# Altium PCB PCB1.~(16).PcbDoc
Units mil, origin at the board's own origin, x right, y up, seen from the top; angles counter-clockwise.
Board outline 5880 x 2260 mil, 2 copper layers (Top Layer, Bottom Layer); 100 components, 175 nets, 460 pads, 120 vias.
Unrouted connection lines stored in the file: 16.
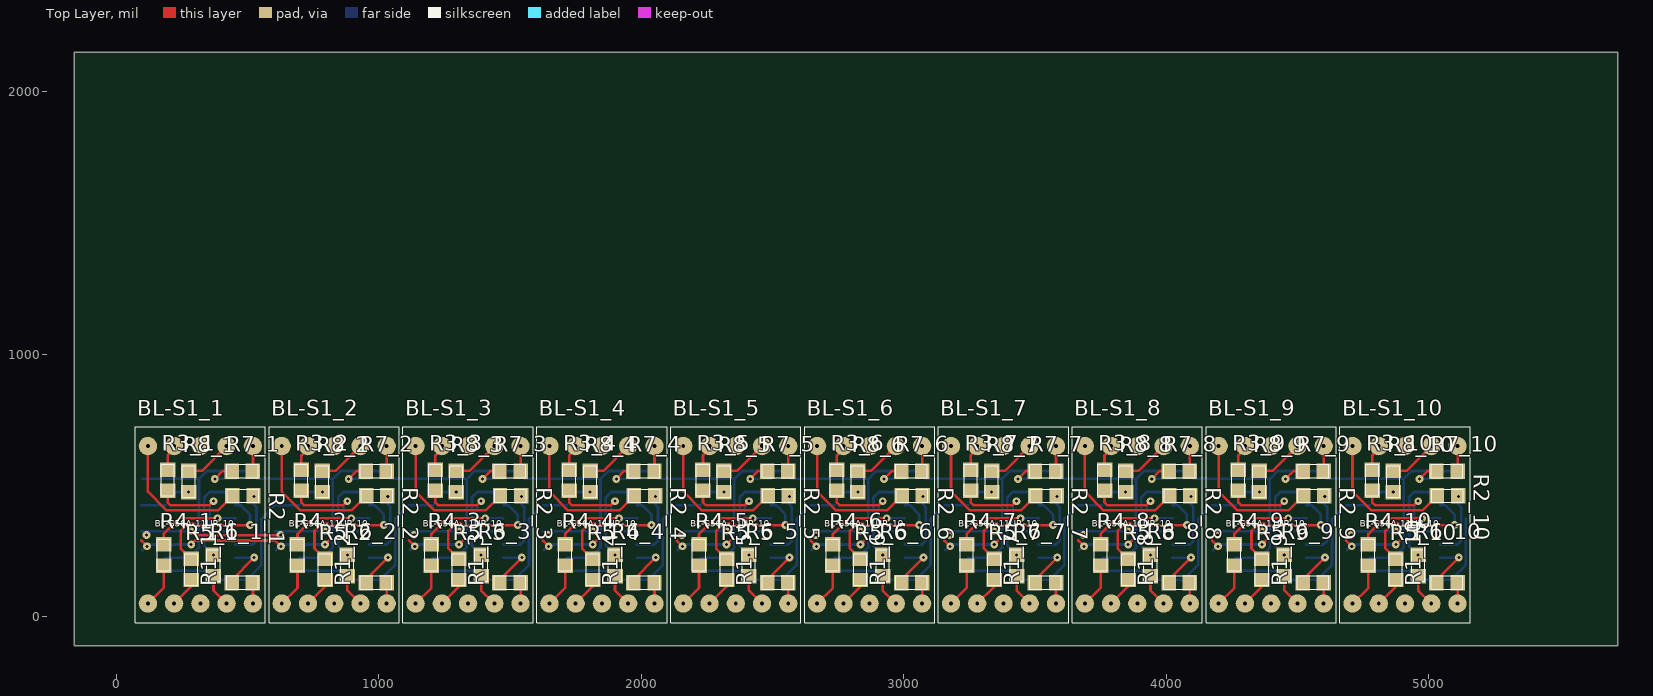
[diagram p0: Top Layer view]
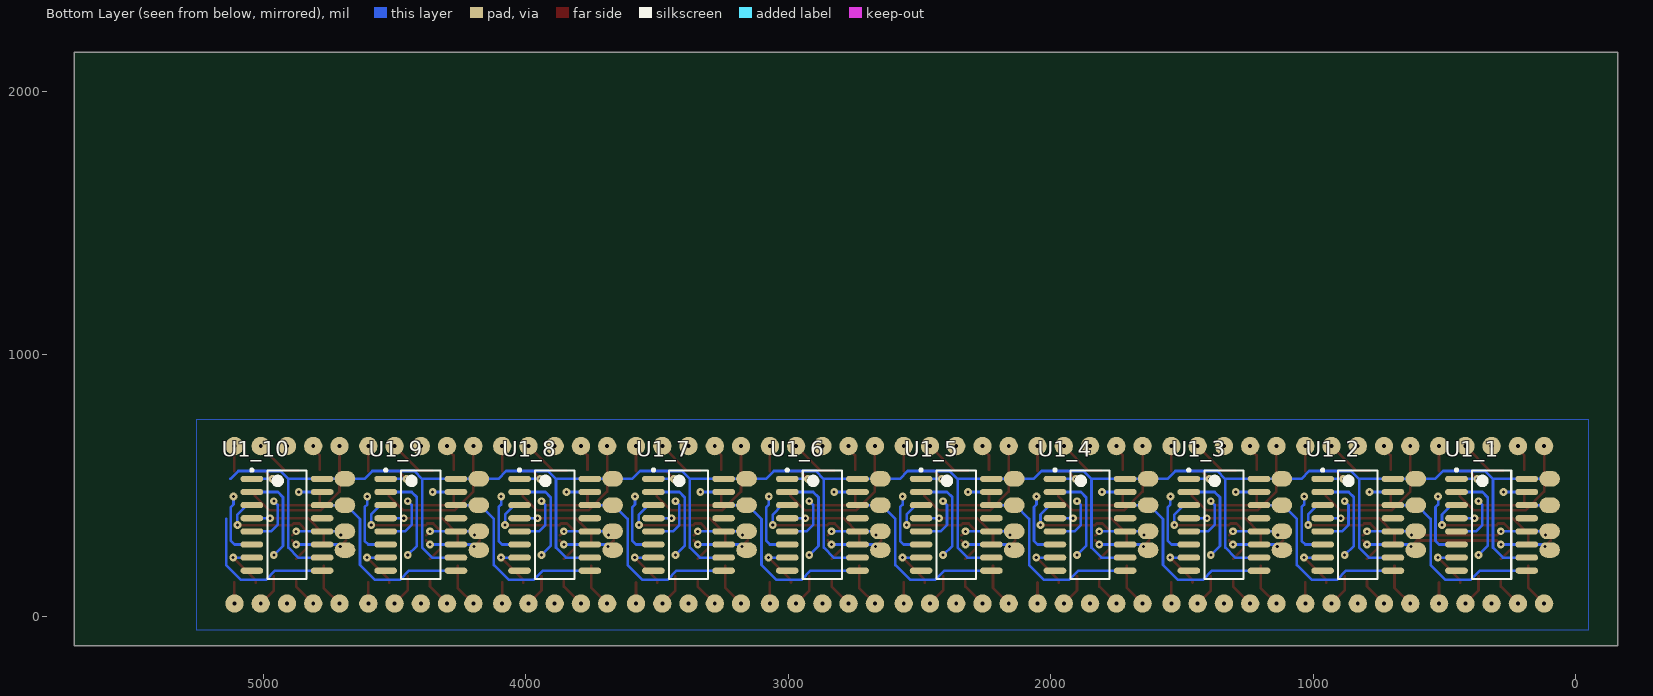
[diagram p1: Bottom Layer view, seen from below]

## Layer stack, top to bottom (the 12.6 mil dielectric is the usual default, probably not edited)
Top Solder: solder mask 0.4, Solder Resist, Dk 3.5
Top Layer: signal copper 1.4
Dielectric 1: dielectric 12.6, FR-4, Dk 4.8
Bottom Layer: signal copper 1.4
Bottom Solder: solder mask 0.4, Solder Resist, Dk 3.5

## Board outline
-160,-110 -160,2150 5720,2150 5720,-110 1430,-110

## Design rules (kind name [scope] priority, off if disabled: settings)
Clearance [All] p1: gap=5
MinimumSolderMaskSliver [All] p1 off: minsoldermaskwidth=10
PolygonConnect [All] p1: connectstyle=Relief reliefconductorwidth=10 reliefentries=4 polygonreliefangle="90 Angle" airgapwidth=15
RoomDefinition 10 [InComponentClass('10')] p1: confinementstyle=ConfineIn formatcopy=TRUE lockcomponents=TRUE outline 4645,-50 4645,750 5162,750 5162,-50
RoomDefinition 9 [InComponentClass('9')] p2: confinementstyle=ConfineIn formatcopy=TRUE lockcomponents=TRUE outline 4135,-50 4135,750 4652,750 4652,-50
RoomDefinition 8 [InComponentClass('8')] p3: confinementstyle=ConfineIn formatcopy=TRUE lockcomponents=TRUE outline 3625,-50 3625,750 4142,750 4142,-50
RoomDefinition 7 [InComponentClass('7')] p4: confinementstyle=ConfineIn formatcopy=TRUE lockcomponents=TRUE outline 3115,-50 3115,750 3632,750 3632,-50
RoomDefinition 6 [InComponentClass('6')] p5: confinementstyle=ConfineIn formatcopy=TRUE lockcomponents=TRUE outline 2605,-50 2605,750 3122,750 3122,-50
RoomDefinition 5 [InComponentClass('5')] p6: confinementstyle=ConfineIn formatcopy=TRUE lockcomponents=TRUE outline 2095,-50 2095,750 2612,750 2612,-50
RoomDefinition 4 [InComponentClass('4')] p7: confinementstyle=ConfineIn formatcopy=TRUE lockcomponents=TRUE outline 1585,-50 1585,750 2102,750 2102,-50
RoomDefinition 2 [InComponentClass('2')] p8: confinementstyle=ConfineIn formatcopy=TRUE lockcomponents=TRUE outline 565,-50 565,750 1082,750 1082,-50
RoomDefinition 1 [InComponentClass('1')] p9: confinementstyle=ConfineIn formatcopy=TRUE lockcomponents=FALSE outline 55,-50 55,750 572,750 572,-50
RoomDefinition 3 [InComponentClass('3')] p10: confinementstyle=ConfineIn formatcopy=TRUE lockcomponents=TRUE outline 1075,-50 1075,750 1592,750 1592,-50
RoutingVias [All] p1: holewidth=11.81 width=29.53 viastyle="Through Hole" minholewidth=11.81 minwidth=29.53 maxholewidth=28 maxwidth=70
SilkToBoardRegionClearance [All] p1 off:
SilkToSilkClearance [All] p1 off: silktosilkclearance=10
SilkToSolderMaskClearance [IsPad] p1 off: minsilkscreentomaskgap=10 clearancetoexposedcopper=TRUE
SolderMaskExpansion [All] p1: expansion=4
Width [All] p1: maxlimit=10 minlimit=7.87 preferedwidth=10
26 further rules are at their usual default settings.

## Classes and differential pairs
component class 6: BL-S1_6 R1_6 R2_6 R3_6 R4_6 R5_6 R6_6 R7_6 R8_6 U1_6
component class 5: BL-S1_5 R1_5 R2_5 R3_5 R4_5 R5_5 R6_5 R7_5 R8_5 U1_5
component class 1: BL-S1_1 R1_1 R2_1 R3_1 R4_1 R5_1 R6_1 R7_1 R8_1 U1_1
component class 2: BL-S1_2 R1_2 R2_2 R3_2 R4_2 R5_2 R6_2 R7_2 R8_2 U1_2
component class 3: BL-S1_3 R1_3 R2_3 R3_3 R4_3 R5_3 R6_3 R7_3 R8_3 U1_3
component class 4: BL-S1_4 R1_4 R2_4 R3_4 R4_4 R5_4 R6_4 R7_4 R8_4 U1_4
channel class Sheet2: 1 2 3 4 5 6 7 8 9 10
component class 7: BL-S1_7 R1_7 R2_7 R3_7 R4_7 R5_7 R6_7 R7_7 R8_7 U1_7
component class 8: BL-S1_8 R1_8 R2_8 R3_8 R4_8 R5_8 R6_8 R7_8 R8_8 U1_8
component class 9: BL-S1_9 R1_9 R2_9 R3_9 R4_9 R5_9 R6_9 R7_9 R8_9 U1_9
component class 10: BL-S1_10 R1_10 R2_10 R3_10 R4_10 R5_10 R6_10 R7_10 R8_10 U1_10

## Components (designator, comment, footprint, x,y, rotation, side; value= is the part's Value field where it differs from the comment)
BL-S1_1 "BL-S56A-11UR" BL-S56A-11UR 71.97,350 r0 top (schematic designator BL-S1)
BL-S1_2 "BL-S56A-11UR" BL-S56A-11UR 581.97,350 r0 top locked (schematic designator BL-S1)
BL-S1_3 "BL-S56A-11UR" BL-S56A-11UR 1091.97,350 r0 top (schematic designator BL-S1)
BL-S1_4 "BL-S56A-11UR" BL-S56A-11UR 1601.97,350 r0 top (schematic designator BL-S1)
BL-S1_5 "BL-S56A-11UR" BL-S56A-11UR 2111.97,350 r0 top (schematic designator BL-S1)
BL-S1_6 "BL-S56A-11UR" BL-S56A-11UR 2621.97,350 r0 top (schematic designator BL-S1)
BL-S1_7 "BL-S56A-11UR" BL-S56A-11UR 3131.97,350 r0 top (schematic designator BL-S1)
BL-S1_8 "BL-S56A-11UR" BL-S56A-11UR 3641.97,350 r0 top (schematic designator BL-S1)
BL-S1_9 "BL-S56A-11UR" BL-S56A-11UR 4151.97,350 r0 top (schematic designator BL-S1)
BL-S1_10 "BL-S56A-11UR" BL-S56A-11UR 4661.97,350 r0 top (schematic designator BL-S1)
R1_1 "310R" Res0805 480,130 r180 top (schematic designator R1)
R1_2 "310R" Res0805 990,130 r180 top (schematic designator R1)
R1_3 "310R" Res0805 1500,130 r180 top (schematic designator R1)
R1_4 "310R" Res0805 2010,130 r180 top (schematic designator R1)
R1_5 "310R" Res0805 2520,130 r180 top (schematic designator R1)
R1_6 "310R" Res0805 3030,130 r180 top (schematic designator R1)
R1_7 "310R" Res0805 3540,130 r180 top (schematic designator R1)
R1_8 "310R" Res0805 4050,130 r180 top (schematic designator R1)
R1_9 "310R" Res0805 4560,130 r180 top (schematic designator R1)
R1_10 "310R" Res0805 5070,130 r180 top (schematic designator R1)
R2_1 "310R" Res0805 482.05,460 r0 top (schematic designator R2)
R2_2 "310R" Res0805 992.05,460 r0 top (schematic designator R2)
R2_3 "310R" Res0805 1502.05,460 r0 top (schematic designator R2)
R2_4 "310R" Res0805 2012.05,460 r0 top (schematic designator R2)
R2_5 "310R" Res0805 2522.05,460 r0 top (schematic designator R2)
R2_6 "310R" Res0805 3032.05,460 r0 top (schematic designator R2)
R2_7 "310R" Res0805 3542.05,460 r0 top (schematic designator R2)
R2_8 "310R" Res0805 4052.05,460 r0 top (schematic designator R2)
R2_9 "310R" Res0805 4562.05,460 r0 top (schematic designator R2)
R2_10 "310R" Res0805 5072.05,460 r0 top (schematic designator R2)
R3_1 "310R" Res0805 195,520 r270 top (schematic designator R3)
R3_2 "310R" Res0805 705,520 r270 top (schematic designator R3)
R3_3 "310R" Res0805 1215,520 r270 top (schematic designator R3)
R3_4 "310R" Res0805 1725,520 r270 top (schematic designator R3)
R3_5 "310R" Res0805 2235,520 r270 top (schematic designator R3)
R3_6 "310R" Res0805 2745,520 r270 top (schematic designator R3)
R3_7 "310R" Res0805 3255,520 r270 top (schematic designator R3)
R3_8 "310R" Res0805 3765,520 r270 top (schematic designator R3)
R3_9 "310R" Res0805 4275,520 r270 top (schematic designator R3)
R3_10 "310R" Res0805 4785,520 r270 top (schematic designator R3)
R4_1 "310R" Res0805 180,235 r90 top (schematic designator R4)
R4_2 "310R" Res0805 690,235 r90 top (schematic designator R4)
R4_3 "310R" Res0805 1200,235 r90 top (schematic designator R4)
R4_4 "310R" Res0805 1710,235 r90 top (schematic designator R4)
R4_5 "310R" Res0805 2220,235 r90 top (schematic designator R4)
R4_6 "310R" Res0805 2730,235 r90 top (schematic designator R4)
R4_7 "310R" Res0805 3240,235 r90 top (schematic designator R4)
R4_8 "310R" Res0805 3750,235 r90 top (schematic designator R4)
R4_9 "310R" Res0805 4260,235 r90 top (schematic designator R4)
R4_10 "310R" Res0805 4770,235 r90 top (schematic designator R4)
R5_1 "310R" Res0805 285,180 r90 top (schematic designator R5)
R5_2 "310R" Res0805 795,180 r90 top (schematic designator R5)
R5_3 "310R" Res0805 1305,180 r90 top (schematic designator R5)
R5_4 "310R" Res0805 1815,180 r90 top (schematic designator R5)
R5_5 "310R" Res0805 2325,180 r90 top (schematic designator R5)
R5_6 "310R" Res0805 2835,180 r90 top (schematic designator R5)
R5_7 "310R" Res0805 3345,180 r90 top (schematic designator R5)
R5_8 "310R" Res0805 3855,180 r90 top (schematic designator R5)
R5_9 "310R" Res0805 4365,180 r90 top (schematic designator R5)
R5_10 "310R" Res0805 4875,180 r90 top (schematic designator R5)
R6_1 "310R" Res0805 370,195 r90 top (schematic designator R6)
R6_2 "310R" Res0805 880,195 r90 top (schematic designator R6)
R6_3 "310R" Res0805 1390,195 r90 top (schematic designator R6)
R6_4 "310R" Res0805 1900,195 r90 top (schematic designator R6)
R6_5 "310R" Res0805 2410,195 r90 top (schematic designator R6)
R6_6 "310R" Res0805 2920,195 r90 top (schematic designator R6)
R6_7 "310R" Res0805 3430,195 r90 top (schematic designator R6)
R6_8 "310R" Res0805 3940,195 r90 top (schematic designator R6)
R6_9 "310R" Res0805 4450,195 r90 top (schematic designator R6)
R6_10 "310R" Res0805 4960,195 r90 top (schematic designator R6)
R7_1 "310R" Res0805 480,555 r180 top (schematic designator R7)
R7_2 "310R" Res0805 990,555 r180 top (schematic designator R7)
R7_3 "310R" Res0805 1500,555 r180 top (schematic designator R7)
R7_4 "310R" Res0805 2010,555 r180 top (schematic designator R7)
R7_5 "310R" Res0805 2520,555 r180 top (schematic designator R7)
R7_6 "310R" Res0805 3030,555 r180 top (schematic designator R7)
R7_7 "310R" Res0805 3540,555 r180 top (schematic designator R7)
R7_8 "310R" Res0805 4050,555 r180 top (schematic designator R7)
R7_9 "310R" Res0805 4560,555 r180 top (schematic designator R7)
R7_10 "310R" Res0805 5070,555 r180 top (schematic designator R7)
R8_1 "310R" Res0805 275,515 r270 top (schematic designator R8)
R8_2 "310R" Res0805 785,515 r270 top (schematic designator R8)
R8_3 "310R" Res0805 1295,515 r270 top (schematic designator R8)
R8_4 "310R" Res0805 1805,515 r270 top (schematic designator R8)
R8_5 "310R" Res0805 2315,515 r270 top (schematic designator R8)
R8_6 "310R" Res0805 2825,515 r270 top (schematic designator R8)
R8_7 "310R" Res0805 3335,515 r270 top (schematic designator R8)
R8_8 "310R" Res0805 3845,515 r270 top (schematic designator R8)
R8_9 "310R" Res0805 4355,515 r270 top (schematic designator R8)
R8_10 "310R" Res0805 4865,515 r270 top (schematic designator R8)
U1_1 "HD74HC595FP" PRSP0016DH-B_N 320,350 r180 bottom (schematic designator U1)
U1_2 "HD74HC595FP" PRSP0016DH-B_N 830,350 r180 bottom (schematic designator U1)
U1_3 "HD74HC595FP" PRSP0016DH-B_N 1340,350 r180 bottom (schematic designator U1)
U1_4 "HD74HC595FP" PRSP0016DH-B_N 1850,350 r180 bottom (schematic designator U1)
U1_5 "HD74HC595FP" PRSP0016DH-B_N 2360,350 r180 bottom (schematic designator U1)
U1_6 "HD74HC595FP" PRSP0016DH-B_N 2870,350 r180 bottom (schematic designator U1)
U1_7 "HD74HC595FP" PRSP0016DH-B_N 3380,350 r180 bottom (schematic designator U1)
U1_8 "HD74HC595FP" PRSP0016DH-B_N 3890,350 r180 bottom (schematic designator U1)
U1_9 "HD74HC595FP" PRSP0016DH-B_N 4400,350 r180 bottom (schematic designator U1)
U1_10 "HD74HC595FP" PRSP0016DH-B_N 4910,350 r180 bottom (schematic designator U1)

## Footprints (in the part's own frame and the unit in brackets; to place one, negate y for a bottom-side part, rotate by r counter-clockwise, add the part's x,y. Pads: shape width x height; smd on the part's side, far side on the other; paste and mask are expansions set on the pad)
BL-S56A-11UR [mil]
  round 70 hole 15: 1(48.03,-300) 2(148.03,-300) 3(248.03,-300) 4(348.03,-300) 5(448.03,-300) 6(448.03,300) 7(348.03,300) 8(248.03,300) 9(148.03,300) 10(48.03,300)
  silkscreen extent 0,-374 496,374, body extent 0,-374 496,374, height 315
PRSP0016DH-B_N [mm] "SOP, 16-Leads, Body 10.06x5.5mm, Pitch 1.27mm, IPC Medium Density"
  oval 2.2x0.6 smd: 1(-3.4,4.445) 2(-3.4,3.175) 3(-3.4,1.905) 4(-3.4,0.635) 5(-3.4,-0.635) 6(-3.4,-1.905) 7(-3.4,-3.175) 8(-3.4,-4.445) 9(3.4,-4.445) 10(3.4,-3.175) 11(3.4,-1.905) 12(3.4,-0.635) 13(3.4,0.635) 14(3.4,1.905) 15(3.4,3.175) 16(3.4,4.445)
  silkscreen extent -3.52,-5.25 1.9,5.42, body extent -2.7,-5.25 2.7,5.25, height 2.2
Res0805 [mm]
  rect 1.4x1.5 smd: 1(-1.025,0) 2(1.025,0)
  silkscreen extent -1.52,-0.64 1.52,0.64, body extent -1.15,-0.67 1.15,0.68, height 0.76

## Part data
BL-S1_1 BL-S1_2 BL-S1_3 BL-S1_4 BL-S1_5 BL-S1_6 BL-S1_7 BL-S1_8 BL-S1_9 BL-S1_10: library part Component_1
R1_1 R1_2 R1_3 R1_4 R1_5 R1_6 R1_7 R1_8 R1_9 R1_10 R2_1 R2_2 R2_3 R2_4 R2_5 R2_6 R2_7 R2_8 R2_9 R2_10 R3_1 R3_2 R3_3 R3_4 R3_5 R3_6 R3_7 R3_8 R3_9 R3_10 R4_1 R4_2 R4_3 R4_4 R4_5 R4_6 R4_7 R4_8 R4_9 R4_10 R5_1 R5_2 R5_3 R5_4 R5_5 R5_6 R5_7 R5_8 R5_9 R5_10 R6_1 R6_2 R6_3 R6_4 R6_5 R6_6 R6_7 R6_8 R6_9 R6_10 R7_1 R7_2 R7_3 R7_4 R7_5 R7_6 R7_7 R7_8 R7_9 R7_10 R8_1 R8_2 R8_3 R8_4 R8_5 R8_6 R8_7 R8_8 R8_9 R8_10: library part Res1, "Resistor"
U1_1 U1_2 U1_3 U1_4 U1_5 U1_6 U1_7 U1_8 U1_9 U1_10: "8-bit Shift Register / Latch with 3-State Outputs"

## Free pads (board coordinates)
  oval 78.74x59.06 smd far side: 8(99.06,525) 8(609.06,525) 8(1119.06,525) 8(1629.06,525) 8(2139.06,525) 8(2649.06,525) 8(3159.06,525) 8(3669.06,525) 8(4179.06,525) 8(4689.06,525) 9(99.06,425) 9(609.06,425) 9(1119.06,425) 9(1629.06,425) 9(2139.06,425) 9(2649.06,425) 9(3159.06,425) 9(3669.06,425) 9(4179.06,425) 9(4689.06,425) 10(99.06,325) 10(609.06,325) 10(1119.06,325) 10(1629.06,325) 10(2139.06,325) 10(2649.06,325) 10(3159.06,325) 10(3669.06,325) 10(4179.06,325) 10(4689.06,325) 11(99,254) 11(609,254) 11(1119,254) 11(1629,254) 11(2139,254) 11(2649,254) 11(3159,254) 11(3669,254) 11(4179,254) 11(4689,254)

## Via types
v1: diameter 29.53, hole 11.81, Top Layer to Bottom Layer, tented both sides, 80 vias
v2: diameter 29.53, hole 11.81, Top Layer to Bottom Layer, 40 vias

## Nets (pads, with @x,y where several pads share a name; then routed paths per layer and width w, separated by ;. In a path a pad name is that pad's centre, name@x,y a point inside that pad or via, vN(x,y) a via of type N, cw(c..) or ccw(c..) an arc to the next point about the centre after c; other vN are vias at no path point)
+5V: pad.8 U1_1.10 U1_1.16 U1_2.10 U1_2.16 U1_3.10 U1_3.16 U1_4.10 U1_4.16 U1_5.10 U1_5.16 U1_6.10 U1_6.16 U1_7.10 U1_7.16 U1_8.10 U1_8.16 U1_9.10 U1_9.16 U1_10.10 U1_10.16 | length 9862.5
  Bottom Layer w10: pad.8@99.06,525 U1_1.16 315,525 345,555 505,555 535,525 U1_2.16 ; U1_1.10 277.09,225 314.76,262.67 314.76,525 ; pad.8@609.06,525 U1_2.16 ; U1_2.10 787.09,225 824.76,262.67 824.76,525 ; U1_3.10 1297.09,225 1334.76,262.67 1334.76,525 ; U1_4.10 1807.09,225 1844.76,262.67 1844.76,525 ; U1_5.10 2317.09,225 2354.76,262.67 2354.76,525 ; pad.8@2649.06,525 2865,525 2895,555 3055,555 3085,525 U1_7.16 ; U1_6.10 2827.09,225 2864.76,262.67 2864.76,525 ; U1_6.16 2575,525 2545,555 2385,555 2355,525 2139.06,525 2065,525 2035,555 1875,555 1845,525 U1_4.16 1629.06,525 1555,525 1525,555 1365,555 1335,525 U1_3.16 1119.06,525 1045,525 1015,555 855,555 825,525 U1_2.16 ; pad.8@3159.06,525 3375,525 3405,555 3565,555 3595,525 U1_8.16 ; U1_7.10 3337.09,225 3374.76,262.67 3374.76,525 ; pad.8@3669.06,525 3885,525 3915,555 4075,555 4105,525 U1_9.16 ; U1_8.10 3847.09,225 3884.76,262.67 3884.76,525 ; pad.8@4179.06,525 4395,525 4425,555 4585,555 4615,525 U1_10.16 ; U1_9.10 4357.09,225 4394.76,262.67 4394.76,525 ; pad.8@4689.06,525 4905,525 4935,555 5095,555 5125,525 ; U1_10.10 4867.09,225 4904.76,262.67 4904.76,525
GND: BL-S1_1.3 BL-S1_1.8 BL-S1_2.3 BL-S1_2.8 BL-S1_3.3 BL-S1_3.8 BL-S1_4.3 BL-S1_4.8 BL-S1_5.3 BL-S1_5.8 BL-S1_6.3 BL-S1_6.8 BL-S1_7.3 BL-S1_7.8 BL-S1_8.3 BL-S1_8.8 BL-S1_9.3 BL-S1_9.8 BL-S1_10.3 BL-S1_10.8 U1_1.8 U1_1.13 U1_2.8 U1_2.13 U1_3.8 U1_3.13 U1_4.8 U1_4.13 U1_5.8 U1_5.13 U1_6.8 U1_6.13 U1_7.8 U1_7.13 U1_8.8 U1_8.13 U1_9.8 U1_9.13 U1_10.8 U1_10.13
L_A_1: BL-S1_1.7 R8_1.1 | length 184.2
  Top Layer w10: R8_1.1 325.35,555.35 BL-S1_1.7
L_A_2: BL-S1_2.7 R8_2.1 | length 184.2
  Top Layer w10: R8_2.1 835.35,555.35 BL-S1_2.7
L_A_3: BL-S1_3.7 R8_3.1 | length 184.2
  Top Layer w10: R8_3.1 1345.35,555.35 BL-S1_3.7
L_A_4: BL-S1_4.7 R8_4.1 | length 184.2
  Top Layer w10: R8_4.1 1855.35,555.35 BL-S1_4.7
L_A_5: BL-S1_5.7 R8_5.1 | length 184.2
  Top Layer w10: R8_5.1 2365.36,555.36 BL-S1_5.7
L_A_6: BL-S1_6.7 R8_6.1 | length 184.2
  Top Layer w10: R8_6.1 2875.36,555.36 BL-S1_6.7
L_A_7: BL-S1_7.7 R8_7.1 | length 184.2
  Top Layer w10: R8_7.1 3385.36,555.36 BL-S1_7.7
L_A_8: BL-S1_8.7 R8_8.1 | length 184.2
  Top Layer w10: R8_8.1 3895.36,555.36 BL-S1_8.7
L_A_9: BL-S1_9.7 R8_9.1 | length 184.2
  Top Layer w10: R8_9.1 4405.36,555.36 BL-S1_9.7
L_A_10: BL-S1_10.7 R8_10.1 | length 184.2
  Top Layer w10: R8_10.1 4915.36,555.36 BL-S1_10.7
L_B_1: BL-S1_1.6 R7_1.1 | length 95.1
  Top Layer w10: BL-S1_1.6 520.35,649.65 R7_1.1
L_B_2: BL-S1_2.6 R7_2.1 | length 95.1
  Top Layer w10: BL-S1_2.6 1030.35,649.65 R7_2.1
L_B_3: BL-S1_3.6 R7_3.1 | length 95.1
  Top Layer w10: BL-S1_3.6 1540.35,649.65 R7_3.1
L_B_4: BL-S1_4.6 R7_4.1 | length 95.1
  Top Layer w10: BL-S1_4.6 2050.35,649.65 R7_4.1
L_B_5: BL-S1_5.6 R7_5.1 | length 95.1
  Top Layer w10: BL-S1_5.6 2560.35,649.65 R7_5.1
L_B_6: BL-S1_6.6 R7_6.1 | length 95.1
  Top Layer w10: BL-S1_6.6 3070.35,649.65 R7_6.1
L_B_7: BL-S1_7.6 R7_7.1 | length 95.1
  Top Layer w10: BL-S1_7.6 3580.35,649.65 R7_7.1
L_B_8: BL-S1_8.6 R7_8.1 | length 95.1
  Top Layer w10: BL-S1_8.6 4090.35,649.65 R7_8.1
L_B_9: BL-S1_9.6 R7_9.1 | length 95.1
  Top Layer w10: BL-S1_9.6 4600.35,649.65 R7_9.1
L_B_10: BL-S1_10.6 R7_10.1 | length 95.1
  Top Layer w10: BL-S1_10.6 5110.35,649.65 R7_10.1
L_C_1: BL-S1_1.4 R6_1.1 | length 125.4
  Top Layer w10: R6_1.1 370,100 BL-S1_1.4
L_C_2: BL-S1_2.4 R6_2.1 | length 125.4
  Top Layer w10: R6_2.1 880,100 BL-S1_2.4
L_C_3: BL-S1_3.4 R6_3.1 | length 125.4
  Top Layer w10: R6_3.1 1390,100 BL-S1_3.4
L_C_4: BL-S1_4.4 R6_4.1 | length 125.4
  Top Layer w10: R6_4.1 1900,100 BL-S1_4.4
L_C_5: BL-S1_5.4 R6_5.1 | length 125.4
  Top Layer w10: R6_5.1 2410,100 BL-S1_5.4
L_C_6: BL-S1_6.4 R6_6.1 | length 125.4
  Top Layer w10: R6_6.1 2920,100 BL-S1_6.4
L_C_7: BL-S1_7.4 R6_7.1 | length 125.4
  Top Layer w10: R6_7.1 3430,100 BL-S1_7.4
L_C_8: BL-S1_8.4 R6_8.1 | length 125.4
  Top Layer w10: R6_8.1 3940,100 BL-S1_8.4
L_C_9: BL-S1_9.4 R6_9.1 | length 125.4
  Top Layer w10: R6_9.1 4450,100 BL-S1_9.4
L_C_10: BL-S1_10.4 R6_10.1 | length 125.4
  Top Layer w10: R6_10.1 4960,100 BL-S1_10.4
L_D_1: BL-S1_1.2 R5_1.1 | length 111.6
  Top Layer w10: BL-S1_1.2 285,115 R5_1.1@285,134.65
L_D_2: BL-S1_2.2 R5_2.1 | length 111.6
  Top Layer w10: BL-S1_2.2 795,115 R5_2.1@795,134.65
L_D_3: BL-S1_3.2 R5_3.1 | length 111.6
  Top Layer w10: BL-S1_3.2 1305,115 R5_3.1@1305,134.65
L_D_4: BL-S1_4.2 R5_4.1 | length 111.6
  Top Layer w10: BL-S1_4.2 1815,115 R5_4.1@1815,134.65
L_D_5: BL-S1_5.2 R5_5.1 | length 111.6
  Top Layer w10: BL-S1_5.2 2325,115 R5_5.1@2325,134.65
L_D_6: BL-S1_6.2 R5_6.1 | length 111.6
  Top Layer w10: BL-S1_6.2 2835,115 R5_6.1@2835,134.65
L_D_7: BL-S1_7.2 R5_7.1 | length 111.6
  Top Layer w10: BL-S1_7.2 3345,115 R5_7.1@3345,134.65
L_D_8: BL-S1_8.2 R5_8.1 | length 111.6
  Top Layer w10: BL-S1_8.2 3855,115 R5_8.1@3855,134.65
L_D_9: BL-S1_9.2 R5_9.1 | length 111.6
  Top Layer w10: BL-S1_9.2 4365,115 R5_9.1@4365,134.65
L_D_10: BL-S1_10.2 R5_10.1 | length 111.6
  Top Layer w10: BL-S1_10.2 4875,115 R5_10.1@4875,134.65
L_E_1: BL-S1_1.1 R4_1.1 | length 169.5
  Top Layer w10: BL-S1_1.1 180,110 R4_1.1
L_E_2: BL-S1_2.1 R4_2.1 | length 169.5
  Top Layer w10: BL-S1_2.1 690,110 R4_2.1
L_E_3: BL-S1_3.1 R4_3.1 | length 169.5
  Top Layer w10: BL-S1_3.1 1200,110 R4_3.1
L_E_4: BL-S1_4.1 R4_4.1 | length 169.5
  Top Layer w10: BL-S1_4.1 1710,110 R4_4.1
L_E_5: BL-S1_5.1 R4_5.1 | length 169.5
  Top Layer w10: BL-S1_5.1 2220,110 R4_5.1
L_E_6: BL-S1_6.1 R4_6.1 | length 169.5
  Top Layer w10: BL-S1_6.1 2730,110 R4_6.1
L_E_7: BL-S1_7.1 R4_7.1 | length 169.5
  Top Layer w10: BL-S1_7.1 3240,110 R4_7.1
L_E_8: BL-S1_8.1 R4_8.1 | length 169.5
  Top Layer w10: BL-S1_8.1 3750,110 R4_8.1
L_E_9: BL-S1_9.1 R4_9.1 | length 169.5
  Top Layer w10: BL-S1_9.1 4260,110 R4_9.1
L_E_10: BL-S1_10.1 R4_10.1 | length 169.5
  Top Layer w10: BL-S1_10.1 4770,110 R4_10.1
L_F_1: BL-S1_1.9 R3_1.1 | length 100
  Top Layer w10: R3_1.1 195,615 220,640 BL-S1_1.9
L_F_2: BL-S1_2.9 R3_2.1 | length 100
  Top Layer w10: R3_2.1 705,615 730,640 BL-S1_2.9
L_F_3: BL-S1_3.9 R3_3.1 | length 100
  Top Layer w10: R3_3.1 1215,615 1240,640 BL-S1_3.9
L_F_4: BL-S1_4.9 R3_4.1 | length 100
  Top Layer w10: R3_4.1 1725,615 1750,640 BL-S1_4.9
L_F_5: BL-S1_5.9 R3_5.1 | length 100
  Top Layer w10: R3_5.1 2235,615 2260,640 BL-S1_5.9
L_F_6: BL-S1_6.9 R3_6.1 | length 100
  Top Layer w10: R3_6.1 2745,615 2770,640 BL-S1_6.9
L_F_7: BL-S1_7.9 R3_7.1 | length 100
  Top Layer w10: R3_7.1 3255,615 3280,640 BL-S1_7.9
L_F_8: BL-S1_8.9 R3_8.1 | length 100
  Top Layer w10: R3_8.1 3765,615 3790,640 BL-S1_8.9
L_F_9: BL-S1_9.9 R3_9.1 | length 100
  Top Layer w10: R3_9.1 4275,615 4300,640 BL-S1_9.9
L_F_10: BL-S1_10.9 R3_10.1 | length 100
  Top Layer w10: R3_10.1 4785,615 4810,640 BL-S1_10.9
L_G_1: BL-S1_1.10 R2_1.1 | length 547.9
  Top Layer w10: BL-S1_1.10 120,476.35 191.58,404.76 386.46,404.76 R2_1.1
L_G_2: BL-S1_2.10 R2_2.1 | length 547.9
  Top Layer w10: BL-S1_2.10 630,476.35 701.58,404.76 896.46,404.76 R2_2.1
L_G_3: BL-S1_3.10 R2_3.1 | length 547.9
  Top Layer w10: BL-S1_3.10 1140,476.35 1211.58,404.76 1406.46,404.76 R2_3.1
L_G_4: BL-S1_4.10 R2_4.1 | length 547.9
  Top Layer w10: BL-S1_4.10 1650,476.35 1721.58,404.76 1916.46,404.76 R2_4.1
L_G_5: BL-S1_5.10 R2_5.1 | length 547.9
  Top Layer w10: BL-S1_5.10 2160,476.35 2231.58,404.76 2426.46,404.76 R2_5.1
L_G_6: BL-S1_6.10 R2_6.1 | length 547.9
  Top Layer w10: BL-S1_6.10 2670,476.35 2741.58,404.76 2936.46,404.76 R2_6.1
L_G_7: BL-S1_7.10 R2_7.1 | length 547.9
  Top Layer w10: BL-S1_7.10 3180,476.35 3251.58,404.76 3446.46,404.76 R2_7.1
L_G_8: BL-S1_8.10 R2_8.1 | length 547.9
  Top Layer w10: BL-S1_8.10 3690,476.35 3761.58,404.76 3956.46,404.76 R2_8.1
L_G_9: BL-S1_9.10 R2_9.1 | length 547.9
  Top Layer w10: BL-S1_9.10 4200,476.35 4271.58,404.76 4466.46,404.76 R2_9.1
L_G_10: BL-S1_10.10 R2_10.1 | length 547.9
  Top Layer w10: BL-S1_10.10 4710,476.35 4781.58,404.76 4976.46,404.76 R2_10.1
L_H_1: BL-S1_1.5 R1_1.1 | length 80.1
  Top Layer w10: BL-S1_1.5 520.35,50.35 R1_1.1
L_H_2: BL-S1_2.5 R1_2.1 | length 80.1
  Top Layer w10: BL-S1_2.5 1030.35,50.35 R1_2.1
L_H_3: BL-S1_3.5 R1_3.1 | length 80.1
  Top Layer w10: BL-S1_3.5 1540.35,50.35 R1_3.1
L_H_4: BL-S1_4.5 R1_4.1 | length 80.1
  Top Layer w10: BL-S1_4.5 2050.35,50.35 R1_4.1
L_H_5: BL-S1_5.5 R1_5.1 | length 80.1
  Top Layer w10: BL-S1_5.5 2560.35,50.35 R1_5.1
L_H_6: BL-S1_6.5 R1_6.1 | length 80.1
  Top Layer w10: BL-S1_6.5 3070.35,50.35 R1_6.1
L_H_7: BL-S1_7.5 R1_7.1 | length 80.1
  Top Layer w10: BL-S1_7.5 3580.35,50.35 R1_7.1
L_H_8: BL-S1_8.5 R1_8.1 | length 80.1
  Top Layer w10: BL-S1_8.5 4090.35,50.35 R1_8.1
L_H_9: BL-S1_9.5 R1_9.1 | length 80.1
  Top Layer w10: BL-S1_9.5 4600.35,50.35 R1_9.1
L_H_10: BL-S1_10.5 R1_10.1 | length 80.1
  Top Layer w10: BL-S1_10.5 5110.35,50.35 R1_10.1
NetR1_1_2: R1_1.2 U1_1.7 | length 201.5
  Top Layer w10: R1_1.2 439.65,139.65 v1(525,225)
  Bottom Layer w10: U1_1.7 v1(525,225)
NetR1_2_2: R1_2.2 U1_2.7 | length 201.5
  Top Layer w10: R1_2.2 949.65,139.65 v1(1035,225)
  Bottom Layer w10: U1_2.7 v1(1035,225)
NetR1_3_2: R1_3.2 U1_3.7 | length 201.5
  Top Layer w10: R1_3.2 1459.65,139.65 v1(1545,225)
  Bottom Layer w10: U1_3.7 v1(1545,225)
NetR1_4_2: R1_4.2 U1_4.7 | length 201.5
  Top Layer w10: R1_4.2 1969.65,139.65 v1(2055,225)
  Bottom Layer w10: U1_4.7 v1(2055,225)
NetR1_5_2: R1_5.2 U1_5.7 | length 201.5
  Top Layer w10: R1_5.2 2479.65,139.65 v1(2565,225)
  Bottom Layer w10: U1_5.7 v1(2565,225)
NetR1_6_2: R1_6.2 U1_6.7 | length 201.5
  Top Layer w10: R1_6.2 2989.65,139.65 v1(3075,225)
  Bottom Layer w10: U1_6.7 v1(3075,225)
NetR1_7_2: R1_7.2 U1_7.7 | length 201.5
  Top Layer w10: R1_7.2 3499.65,139.65 v1(3585,225)
  Bottom Layer w10: U1_7.7 v1(3585,225)
NetR1_8_2: R1_8.2 U1_8.7 | length 201.5
  Top Layer w10: R1_8.2 4009.65,139.65 v1(4095,225)
  Bottom Layer w10: U1_8.7 v1(4095,225)
NetR1_9_2: R1_9.2 U1_9.7 | length 201.5
  Top Layer w10: R1_9.2 4519.65,139.65 v1(4605,225)
  Bottom Layer w10: U1_9.7 v1(4605,225)
NetR1_10_2: R1_10.2 U1_10.7 | length 201.5
  Top Layer w10: R1_10.2 5029.65,139.65 v1(5115,225)
  Bottom Layer w10: U1_10.7 v1(5115,225)
NetR2_1_2: R2_1.2 U1_1.6 | length 258.9
  Bottom Layer w10: U1_1.6 520,275 533.76,288.76 533.76,417.45 524,427.21 v1(524,458)
NetR2_2_2: R2_2.2 U1_2.6 | length 258.9
  Bottom Layer w10: U1_2.6 1030,275 1043.76,288.76 1043.76,417.45 1034,427.21 v1(1034,458)
NetR2_3_2: R2_3.2 U1_3.6 | length 258.9
  Bottom Layer w10: U1_3.6 1540,275 1553.76,288.76 1553.76,417.45 1544,427.21 v1(1544,458)
NetR2_4_2: R2_4.2 U1_4.6 | length 258.9
  Bottom Layer w10: U1_4.6 2050,275 2063.76,288.76 2063.76,417.45 2054,427.21 v1(2054,458)
NetR2_5_2: R2_5.2 U1_5.6 | length 258.9
  Bottom Layer w10: U1_5.6 2560,275 2573.76,288.77 2573.76,417.45 2564,427.21 v1(2564,458)
NetR2_6_2: R2_6.2 U1_6.6 | length 258.9
  Bottom Layer w10: U1_6.6 3070,275 3083.76,288.77 3083.76,417.45 3074,427.21 v1(3074,458)
NetR2_7_2: R2_7.2 U1_7.6 | length 258.9
  Bottom Layer w10: U1_7.6 3580,275 3593.76,288.77 3593.76,417.45 3584,427.21 v1(3584,458)
NetR2_8_2: R2_8.2 U1_8.6 | length 258.9
  Bottom Layer w10: U1_8.6 4090,275 4103.76,288.77 4103.76,417.45 4094,427.21 v1(4094,458)
NetR2_9_2: R2_9.2 U1_9.6 | length 258.9
  Bottom Layer w10: U1_9.6 4600,275 4613.76,288.77 4613.76,417.45 4604,427.21 v1(4604,458)
NetR2_10_2: R2_10.2 U1_10.6 | length 258.9
  Bottom Layer w10: U1_10.6 5110,275 5123.76,288.77 5123.76,417.45 5114,427.21 v1(5114,458)
NetR3_1_2: R3_1.2 U1_1.5 | length 435.2
  Top Layer w10: R3_1.2 195,435 205,425 355,425 v1(370,440)
  Bottom Layer w10: v1(370,440) 355.24,425.24 355.24,349.76 380,325 U1_1.5
NetR3_2_2: R3_2.2 U1_2.5 | length 435.2
  Top Layer w10: R3_2.2 705,435 715,425 865,425 v1(880,440)
  Bottom Layer w10: v1(880,440) 865.24,425.24 865.24,349.76 890,325 U1_2.5
NetR3_3_2: R3_3.2 U1_3.5 | length 435.2
  Top Layer w10: R3_3.2 1215,435 1225,425 1375,425 v1(1390,440)
  Bottom Layer w10: v1(1390,440) 1375.24,425.24 1375.24,349.76 1400,325 U1_3.5
NetR3_4_2: R3_4.2 U1_4.5 | length 435.2
  Top Layer w10: R3_4.2 1725,435 1735,425 1885,425 v1(1900,440)
  Bottom Layer w10: v1(1900,440) 1885.24,425.24 1885.24,349.76 1910,325 U1_4.5
NetR3_5_2: R3_5.2 U1_5.5 | length 435.2
  Top Layer w10: R3_5.2 2235,435 2245,425 2395,425 v1(2410,440)
  Bottom Layer w10: v1(2410,440) 2395.24,425.24 2395.24,349.76 2420,325 U1_5.5
NetR3_6_2: R3_6.2 U1_6.5 | length 435.2
  Top Layer w10: R3_6.2 2745,435 2755,425 2905,425 v1(2920,440)
  Bottom Layer w10: v1(2920,440) 2905.24,425.24 2905.24,349.76 2930,325 U1_6.5
NetR3_7_2: R3_7.2 U1_7.5 | length 435.2
  Top Layer w10: R3_7.2 3255,435 3265,425 3415,425 v1(3430,440)
  Bottom Layer w10: v1(3430,440) 3415.24,425.24 3415.24,349.76 3440,325 U1_7.5
NetR3_8_2: R3_8.2 U1_8.5 | length 435.2
  Top Layer w10: R3_8.2 3765,435 3775,425 3925,425 v1(3940,440)
  Bottom Layer w10: v1(3940,440) 3925.24,425.24 3925.24,349.76 3950,325 U1_8.5
NetR3_9_2: R3_9.2 U1_9.5 | length 435.2
  Top Layer w10: R3_9.2 4275,435 4285,425 4435,425 v1(4450,440)
  Bottom Layer w10: v1(4450,440) 4435.24,425.24 4435.24,349.76 4460,325 U1_9.5
NetR3_10_2: R3_10.2 U1_10.5 | length 435.2
  Top Layer w10: R3_10.2 4785,435 4795,425 4945,425 v1(4960,440)
  Bottom Layer w10: v1(4960,440) 4945.24,425.24 4945.24,349.76 4970,325 U1_10.5
NetR4_1_2: R4_1.2 U1_1.4 | length 338.4
  Top Layer w10: R4_1.2 180,315 240,375 v1(385,375)
  Bottom Layer w10: v1(385,375) U1_1.4
NetR4_2_2: R4_2.2 U1_2.4 | length 338.4
  Top Layer w10: R4_2.2 690,315 750,375 v1(895,375)
  Bottom Layer w10: v1(895,375) U1_2.4
NetR4_3_2: R4_3.2 U1_3.4 | length 338.4
  Top Layer w10: R4_3.2 1200,315 1260,375 v1(1405,375)
  Bottom Layer w10: v1(1405,375) U1_3.4
NetR4_4_2: R4_4.2 U1_4.4 | length 338.4
  Top Layer w10: R4_4.2 1710,315 1770,375 v1(1915,375)
  Bottom Layer w10: v1(1915,375) U1_4.4
NetR4_5_2: R4_5.2 U1_5.4 | length 338.4
  Top Layer w10: R4_5.2 2220,315 2280,375 v1(2425,375)
  Bottom Layer w10: v1(2425,375) U1_5.4
NetR4_6_2: R4_6.2 U1_6.4 | length 338.4
  Top Layer w10: R4_6.2 2730,315 2790,375 v1(2935,375)
  Bottom Layer w10: v1(2935,375) U1_6.4
NetR4_7_2: R4_7.2 U1_7.4 | length 338.4
  Top Layer w10: R4_7.2 3240,315 3300,375 v1(3445,375)
  Bottom Layer w10: v1(3445,375) U1_7.4
NetR4_8_2: R4_8.2 U1_8.4 | length 338.4
  Top Layer w10: R4_8.2 3750,315 3810,375 v1(3955,375)
  Bottom Layer w10: v1(3955,375) U1_8.4
NetR4_9_2: R4_9.2 U1_9.4 | length 338.4
  Top Layer w10: R4_9.2 4260,315 4320,375 v1(4465,375)
  Bottom Layer w10: v1(4465,375) U1_9.4
NetR4_10_2: R4_10.2 U1_10.4 | length 338.4
  Top Layer w10: R4_10.2 4770,315 4830,375 v1(4975,375)
  Bottom Layer w10: v1(4975,375) U1_10.4
NetR5_1_2: R5_1.2 U1_1.3 | length 511.4
  Top Layer w10: R5_1.2 245,260.35 245,327.09 272.91,355 295,355 301,349 v1(509,349)
  Bottom Layer w10: U1_1.3 473,425 509,389 v1(509,349)
NetR5_2_2: R5_2.2 U1_2.3 | length 511.4
  Top Layer w10: R5_2.2 755,260.35 755,327.09 782.91,355 805,355 811,349 v1(1019,349)
  Bottom Layer w10: U1_2.3 983,425 1019,389 v1(1019,349)
NetR5_3_2: R5_3.2 U1_3.3 | length 511.4
  Top Layer w10: R5_3.2 1265,260.35 1265,327.09 1292.91,355 1315,355 1321,349 v1(1529,349)
  Bottom Layer w10: U1_3.3 1493,425 1529,389 v1(1529,349)
NetR5_4_2: R5_4.2 U1_4.3 | length 511.4
  Top Layer w10: R5_4.2 1775,260.35 1775,327.09 1802.91,355 1825,355 1831,349 v1(2039,349)
  Bottom Layer w10: U1_4.3 2003,425 2039,389 v1(2039,349)
NetR5_5_2: R5_5.2 U1_5.3 | length 511.4
  Top Layer w10: R5_5.2 2285,260.36 2285,327.09 2312.91,355 2335,355 2341,349 v1(2549,349)
  Bottom Layer w10: U1_5.3 2513,425 2549,389 v1(2549,349)
NetR5_6_2: R5_6.2 U1_6.3 | length 511.4
  Top Layer w10: R5_6.2 2795,260.36 2795,327.09 2822.91,355 2845,355 2851,349 v1(3059,349)
  Bottom Layer w10: U1_6.3 3023,425 3059,389 v1(3059,349)
NetR5_7_2: R5_7.2 U1_7.3 | length 511.4
  Top Layer w10: R5_7.2 3305,260.36 3305,327.09 3332.91,355 3355,355 3361,349 v1(3569,349)
  Bottom Layer w10: U1_7.3 3533,425 3569,389 v1(3569,349)
NetR5_8_2: R5_8.2 U1_8.3 | length 511.4
  Top Layer w10: R5_8.2 3815,260.36 3815,327.09 3842.91,355 3865,355 3871,349 v1(4079,349)
  Bottom Layer w10: U1_8.3 4043,425 4079,389 v1(4079,349)
NetR5_9_2: R5_9.2 U1_9.3 | length 511.4
  Top Layer w10: R5_9.2 4325,260.36 4325,327.09 4352.91,355 4375,355 4381,349 v1(4589,349)
  Bottom Layer w10: U1_9.3 4553,425 4589,389 v1(4589,349)
NetR5_10_2: R5_10.2 U1_10.3 | length 511.4
  Top Layer w10: R5_10.2 4835,260.36 4835,327.09 4862.91,355 4885,355 4891,349 v1(5099,349)
  Bottom Layer w10: U1_10.3 5063,425 5099,389 v1(5099,349)
NetR6_1_2: R6_1.2 U1_1.2 | length 362
  Top Layer w10: v2(370,235) R6_1.2
  Bottom Layer w10: v2(370,235) 335,270 335,455 355,475 U1_1.2
NetR6_2_2: R6_2.2 U1_2.2 | length 362
  Top Layer w10: v2(880,235) R6_2.2
  Bottom Layer w10: v2(880,235) 845,270 845,455 865,475 U1_2.2
NetR6_3_2: R6_3.2 U1_3.2 | length 362
  Top Layer w10: v2(1390,235) R6_3.2
  Bottom Layer w10: v2(1390,235) 1355,270 1355,455 1375,475 U1_3.2
NetR6_4_2: R6_4.2 U1_4.2 | length 362
  Top Layer w10: v2(1900,235) R6_4.2
  Bottom Layer w10: v2(1900,235) 1865,270 1865,455 1885,475 U1_4.2
NetR6_5_2: R6_5.2 U1_5.2 | length 362
  Top Layer w10: v2(2410,235) R6_5.2
  Bottom Layer w10: v2(2410,235) 2375,270 2375,455 2395,475 U1_5.2
NetR6_6_2: R6_6.2 U1_6.2 | length 362
  Top Layer w10: v2(2920,235) R6_6.2
  Bottom Layer w10: v2(2920,235) 2885,270 2885,455 2905,475 U1_6.2
NetR6_7_2: R6_7.2 U1_7.2 | length 362
  Top Layer w10: v2(3430,235) R6_7.2
  Bottom Layer w10: v2(3430,235) 3395,270 3395,455 3415,475 U1_7.2
NetR6_8_2: R6_8.2 U1_8.2 | length 362
  Top Layer w10: v2(3940,235) R6_8.2
  Bottom Layer w10: v2(3940,235) 3905,270 3905,455 3925,475 U1_8.2
NetR6_9_2: R6_9.2 U1_9.2 | length 362
  Top Layer w10: v2(4450,235) R6_9.2
  Bottom Layer w10: v2(4450,235) 4415,270 4415,455 4435,475 U1_9.2
NetR6_10_2: R6_10.2 U1_10.2 | length 362
  Top Layer w10: v2(4960,235) R6_10.2
  Bottom Layer w10: v2(4960,235) 4925,270 4925,455 4945,475 U1_10.2
NetR7_1_2: R7_1.2 U1_1.1 | length 155.9
  Top Layer w10: v1(375,525) 405,555 R7_1.2
  Bottom Layer w10: v1(375,525) U1_1.1
NetR7_2_2: R7_2.2 U1_2.1 | length 155.9
  Top Layer w10: v1(885,525) 915,555 R7_2.2
  Bottom Layer w10: v1(885,525) U1_2.1
NetR7_3_2: R7_3.2 U1_3.1 | length 155.9
  Top Layer w10: v1(1395,525) 1425,555 R7_3.2
  Bottom Layer w10: v1(1395,525) U1_3.1
NetR7_4_2: R7_4.2 U1_4.1 | length 155.9
  Top Layer w10: v1(1905,525) 1935,555 R7_4.2
  Bottom Layer w10: v1(1905,525) U1_4.1
NetR7_5_2: R7_5.2 U1_5.1 | length 155.9
  Top Layer w10: v1(2415,525) 2445,555 R7_5.2
  Bottom Layer w10: v1(2415,525) U1_5.1
NetR7_6_2: R7_6.2 U1_6.1 | length 155.9
  Top Layer w10: v1(2925,525) 2955,555 R7_6.2
  Bottom Layer w10: v1(2925,525) U1_6.1
NetR7_7_2: R7_7.2 U1_7.1 | length 155.9
  Top Layer w10: v1(3435,525) 3465,555 R7_7.2
  Bottom Layer w10: v1(3435,525) U1_7.1
NetR7_8_2: R7_8.2 U1_8.1 | length 155.9
  Top Layer w10: v1(3945,525) 3975,555 R7_8.2
  Bottom Layer w10: v1(3945,525) U1_8.1
NetR7_9_2: R7_9.2 U1_9.1 | length 155.9
  Top Layer w10: v1(4455,525) 4485,555 R7_9.2
  Bottom Layer w10: v1(4455,525) U1_9.1
NetR7_10_2: R7_10.2 U1_10.1 | length 155.9
  Top Layer w10: v1(4965,525) 4995,555 R7_10.2
  Bottom Layer w10: v1(4965,525) U1_10.1
NetR8_1_2: R8_1.2 U1_1.15 | length 88.9
  Bottom Layer w10: U1_1.15 v2(275,475)
NetR8_2_2: R8_2.2 U1_2.15 | length 88.9
  Bottom Layer w10: U1_2.15 v2(785,475)
NetR8_3_2: R8_3.2 U1_3.15 | length 88.9
  Bottom Layer w10: U1_3.15 v2(1295,475)
NetR8_4_2: R8_4.2 U1_4.15 | length 88.9
  Bottom Layer w10: U1_4.15 v2(1805,475)
NetR8_5_2: R8_5.2 U1_5.15 | length 88.9
  Bottom Layer w10: U1_5.15 v2(2315,475)
NetR8_6_2: R8_6.2 U1_6.15 | length 88.9
  Bottom Layer w10: U1_6.15 v2(2825,475)
NetR8_7_2: R8_7.2 U1_7.15 | length 88.9
  Bottom Layer w10: U1_7.15 v2(3335,475)
NetR8_8_2: R8_8.2 U1_8.15 | length 88.9
  Bottom Layer w10: U1_8.15 v2(3845,475)
NetR8_9_2: R8_9.2 U1_9.15 | length 88.9
  Bottom Layer w10: U1_9.15 v2(4355,475)
NetR8_10_2: R8_10.2 U1_10.15 | length 88.9
  Bottom Layer w10: U1_10.15 v2(4865,475)
NetU1_1_9: pad.9@609.06,425 U1_1.9 U1_2.14 | length 745.1
  Bottom Layer w10: U1_1.9 365,175 400,140 495,140 552,197 552,372 605,425 U1_2.14
NetU1_1_14: pad.9@99.06,425 U1_1.14 | length 91.1
  Bottom Layer w10: pad.9@95,425 U1_1.14
NetU1_2_9: pad.9@1119.06,425 U1_2.9 U1_3.14 | length 745.1
  Bottom Layer w10: U1_2.9 875,175 910,140 1005,140 1062,197 1062,372 1115,425 1119.06,425 U1_3.14
NetU1_3_9: pad.9@1629.06,425 U1_3.9 U1_4.14 | length 745.1
  Bottom Layer w10: U1_3.9 1385,175 1420,140 1515,140 1572,197 1572,372 1625,425 U1_4.14
NetU1_4_9: pad.9@2139.06,425 U1_4.9 U1_5.14 | length 745.1
  Bottom Layer w10: U1_4.9 1895,175 1930,140 2025,140 2082,197 2082,372 2135,425 U1_5.14
NetU1_5_9: pad.9@2649.06,425 U1_5.9 U1_6.14 | length 745.1
  Bottom Layer w10: U1_5.9 2405,175 2440,140 2535,140 2592,197 2592,372 2645,425 U1_6.14
NetU1_6_9: pad.9@3159.06,425 U1_6.9 U1_7.14 | length 745.1
  Bottom Layer w10: U1_6.9 2915,175 2950,140 3045,140 3102,197 3102,372 3155,425 U1_7.14
NetU1_7_9: pad.9@3669.06,425 U1_7.9 U1_8.14 | length 745.1
  Bottom Layer w10: U1_7.9 3425,175 3460,140 3555,140 3612,197 3612,372 3665,425 U1_8.14
NetU1_8_9: pad.9@4179.06,425 U1_8.9 U1_9.14 | length 745.1
  Bottom Layer w10: U1_8.9 3935,175 3970,140 4065,140 4122,197 4122,372 4175,425 U1_9.14
NetU1_9_9: pad.9@4689.06,425 U1_9.9 U1_10.14 | length 745.1
  Bottom Layer w10: U1_9.9 4445,175 4480,140 4575,140 4632,197 4632,372 4685,425 U1_10.14
NetU1_10_9: U1_10.9 | length 579
  Bottom Layer w10: U1_10.9 4955,175 4990,140 5085,140 5142,197 5142,372
SHCP: pad.11 U1_1.11 U1_2.11 U1_3.11 U1_4.11 U1_5.11 U1_6.11 U1_7.11 U1_8.11 U1_9.11 U1_10.11 | length 2775.2
  Top Layer w10: 95,290 v2(117,268) ; v1(285,275) 300,290 605,290 v2(627,268) ; v1(795,275) 810,290 ; 1115,290 v2(1137,268) ; v1(1305,275) 1320,290 ; 1625,290 v2(1647,268) ; v1(1815,275) 1830,290 ; 2135,290 v2(2157,268) ; v1(2325,275) 2340,290 ; 2645,290 v2(2667,268) ; v1(2835,275) 2850,290 ; 3155,290 v2(3177,268) ; v1(3345,275) 3360,290 ; 3665,290 v2(3687,268) ; v1(3855,275) 3870,290 ; 4175,290 v2(4197,268) ; v1(4365,275) 4380,290 ; 4685,290 v2(4707,268) ; v1(4875,275) 4890,290
  Bottom Layer w10: pad.11@99,254 120,275 U1_1.11 v1(285,275) ; pad.11@609,254 630,275 U1_2.11 v1(795,275) ; pad.11@1119,254 1140,275 U1_3.11 v1(1305,275) ; pad.11@1629,254 1650,275 U1_4.11 v1(1815,275) ; pad.11@2139,254 2160,275 U1_5.11 v1(2325,275) ; pad.11@2649,254 2670,275 U1_6.11 v1(2835,275) ; pad.11@3159,254 3180,275 U1_7.11 v1(3345,275) ; pad.11@3669,254 3690,275 U1_8.11 v1(3855,275) ; pad.11@4179,254 4200,275 U1_9.11 v1(4365,275) ; pad.11@4689,254 4710,275 U1_10.11 v1(4875,275)
STCP: pad.10 U1_1.12 U1_2.12 U1_3.12 U1_4.12 U1_5.12 U1_6.12 U1_7.12 U1_8.12 U1_9.12 U1_10.12 | length 2432.1
  Top Layer w10: v1(285,325) 300,310 v2@620,310 ; v1(795,325) 810,310 ; v1(1305,325) 1320,310 ; v1(1815,325) 1830,310 ; v1(2325,325) 2340,310 ; v1(2835,325) 2850,310 ; v1(3345,325) 3360,310 ; v1(3855,325) 3870,310 ; v1(4365,325) 4380,310 ; v1(4875,325) 4890,310
  Bottom Layer w10: pad.10@95,325 U1_1.12 v1(285,325) ; pad.10@605,325 U1_2.12 v1(795,325) ; pad.10@1115,325 U1_3.12 v1(1305,325) ; pad.10@1625,325 U1_4.12 v1(1815,325) ; pad.10@2135,325 U1_5.12 v1(2325,325) ; pad.10@2645,325 U1_6.12 v1(2835,325) ; pad.10@3155,325 U1_7.12 v1(3345,325) ; pad.10@3665,325 U1_8.12 v1(3855,325) ; pad.10@4175,325 U1_9.12 v1(4365,325) ; pad.10@4685,325 U1_10.12 v1(4875,325)
  other v2: 115,311 625,311 1135,311 1645,311 2155,311 2665,311 3175,311 3685,311 4195,311 4705,311

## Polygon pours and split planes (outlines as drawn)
GND on Bottom Layer "Bottom Layer-No Net" (solid, shelved, pour order 0): -50,750 5256,750 5256,-50 -50,-50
